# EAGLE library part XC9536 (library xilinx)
Xilinx CPLD Cells 36 Gates 800
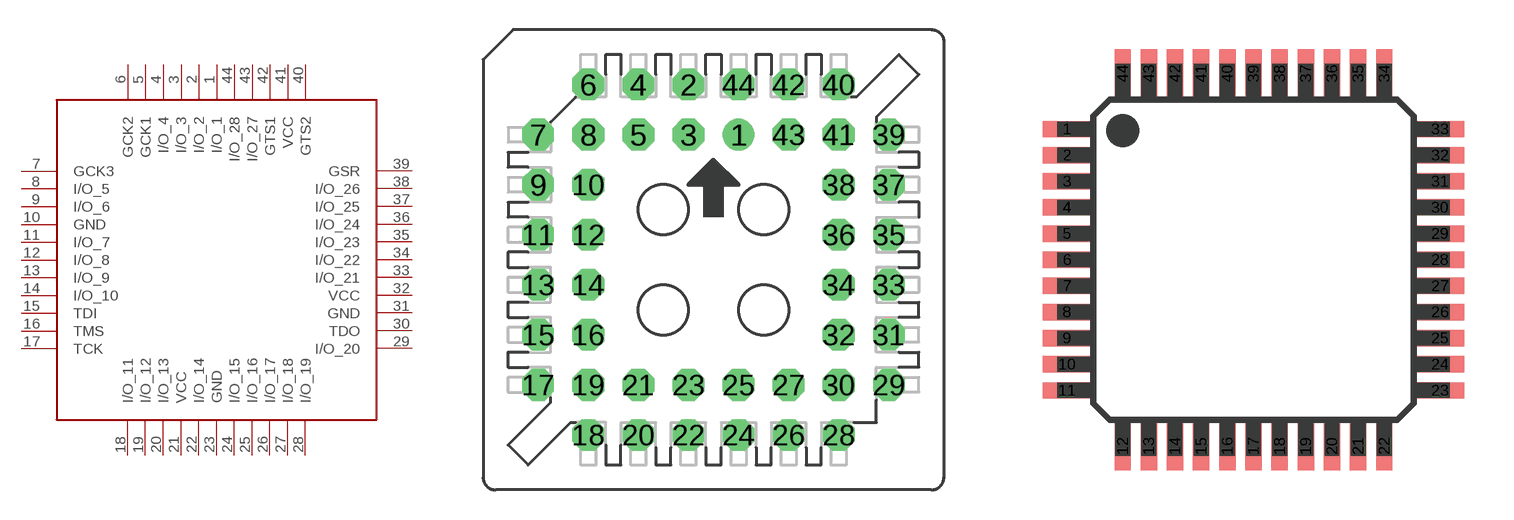
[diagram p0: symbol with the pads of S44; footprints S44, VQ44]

Designator prefix IC

## XC9536PLCC44S  [S44]
1  I/O_1
2  I/O_2
3  I/O_3
4  I/O_4
5  GCK1
6  GCK2
7  GCK3
8  I/O_5
9  I/O_6
10  GND  pwr
11  I/O_7
12  I/O_8
13  I/O_9
14  I/O_10
15  TDI
16  TMS
17  TCK
18  I/O_11
19  I/O_12
20  I/O_13
21  VCC  pwr
22  I/O_14
23  GND  pwr
24  I/O_15
25  I/O_16
26  I/O_17
27  I/O_18
28  I/O_19
29  I/O_20
30  TDO
31  GND  pwr
32  VCC  pwr
33  I/O_21
34  I/O_22
35  I/O_23
36  I/O_24
37  I/O_25
38  I/O_26
39  GSR
40  GTS2
41  VCC  pwr
42  GTS1
43  I/O_27
44  I/O_28

## XC9536VQ44  [VQ44]
1  GCK3
2  I/O_5
3  I/O_6
4  GND  pwr
5  I/O_7
6  I/O_8
7  I/O_9
8  I/O_10
9  TDI
10  TMS
11  TCK
12  I/O_11
13  I/O_12
14  I/O_13
15  VCC  pwr
16  I/O_14
17  GND  pwr
18  I/O_15
19  I/O_16
20  I/O_17
21  I/O_18
22  I/O_19
23  I/O_20
24  TDO
25  GND  pwr
26  VCC  pwr
27  I/O_21
28  I/O_22
29  I/O_23
30  I/O_24
31  I/O_25
32  I/O_26
33  GSR
34  GTS2
35  VCC  pwr
36  GTS1
37  I/O_27
38  I/O_28
39  I/O_1
40  I/O_2
41  I/O_3
42  I/O_4
43  GCK1
44  GCK2

## Footprint S44 (pad centres in mm)
drill 0.813 pad 1.6 round: 1 1.27,5.08
drill 0.813 pad 1.6 octagon: 2 -1.27,7.62; 3 -1.27,5.08; 4 -3.81,7.62; 5 -3.81,5.08; 6 -6.35,7.62; 7 -8.89,5.08; 8 -6.35,5.08; 9 -8.89,2.54; 10 -6.35,2.54; 11 -8.89,0; 12 -6.35,0; 13 -8.89,-2.54; 14 -6.35,-2.54; 15 -8.89,-5.08; 16 -6.35,-5.08; 17 -8.89,-7.62; 18 -6.35,-10.16; 19 -6.35,-7.62; 20 -3.81,-10.16; 21 -3.81,-7.62; 22 -1.27,-10.16; 23 -1.27,-7.62; 24 1.27,-10.16; 25 1.27,-7.62; 26 3.81,-10.16; 27 3.81,-7.62; 28 6.35,-10.16; 29 8.89,-7.62; 30 6.35,-7.62; 31 8.89,-5.08; 32 6.35,-5.08; 33 8.89,-2.54; 34 6.35,-2.54; 35 8.89,0; 36 6.35,0; 37 8.89,2.54; 38 6.35,2.54; 39 8.89,5.08; 40 6.35,7.62; 41 6.35,5.08; 42 3.81,7.62; 43 3.81,5.08; 44 1.27,7.62

## Footprint VQ44 (pad centres in mm)
smd 1.5 x 0.5: 1 -5.7,4; 2 -5.7,3.2; 3 -5.7,2.4; 4 -5.7,1.6; 5 -5.7,0.8; 6 -5.7,0; 7 -5.7,-0.8; 8 -5.7,-1.6; 9 -5.7,-2.4; 10 -5.7,-3.2; 11 -5.7,-4; 23 5.7,-4; 24 5.7,-3.2; 25 5.7,-2.4; 26 5.7,-1.6; 27 5.7,-0.8; 28 5.7,0; 29 5.7,0.8; 30 5.7,1.6; 31 5.7,2.4; 32 5.7,3.2; 33 5.7,4
smd 0.5 x 1.5: 12 -4,-5.7; 13 -3.2,-5.7; 14 -2.4,-5.7; 15 -1.6,-5.7; 16 -0.8,-5.7; 17 0,-5.7; 18 0.8,-5.7; 19 1.6,-5.7; 20 2.4,-5.7; 21 3.2,-5.7; 22 4,-5.7; 34 4,5.7; 35 3.2,5.7; 36 2.4,5.7; 37 1.6,5.7; 38 0.8,5.7; 39 0,5.7; 40 -0.8,5.7; 41 -1.6,5.7; 42 -2.4,5.7; 43 -3.2,5.7; 44 -4,5.7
